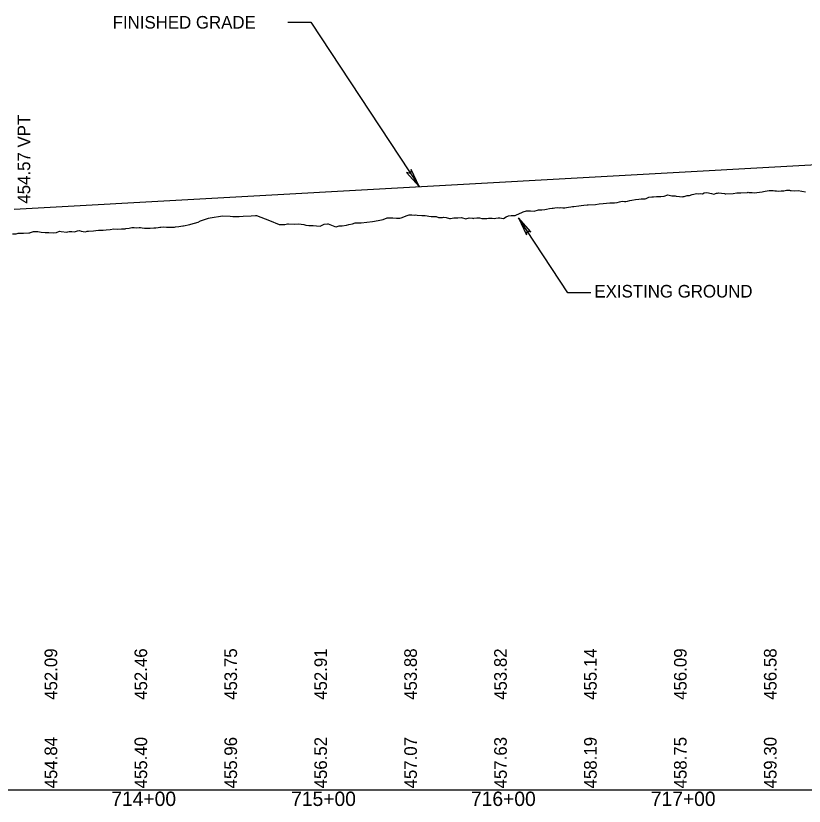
# Model space of a CAD drawing. Extents: x 2017200 to 2047700, y 854850 to 893350.
# Drawn here: x 2024326 to 2024764.4, y 889090.9 to 889530.3 of the extents above; entities that cross this region are included whole.
import ezdxf

# ---------------------------------------------------------------- set-up
doc = ezdxf.new("R2010")
doc.units = 0
for name, color, linetype in [('RD_DDB_Profile_EX', 7, 'Continuous'), ('RD_DDB_Profile_Lbl', 7, 'Continuous'), ('RD_DDB_Profile_PR', 7, 'Continuous'), ('RD_DDB_StaTX', 7, 'Continuous'), ('RD_DDB_StripGrade', 7, 'Continuous'), ('RD_GPK_Profile_Cell', 7, 'Continuous')]:
    doc.layers.add(name, color=color, linetype=linetype)

msp = doc.modelspace()

# ---------------------------------------------------------------- linework, layer by layer
at = {"layer": 'RD_DDB_Profile_EX'}
msp.add_lwpolyline([(2024324.24, 889409.11), (2024326.15, 889409.05), (2024327.38, 889409.46), (2024328.74, 889409.44), (2024329.5, 889409.49), (2024330.18, 889409.57), (2024333.24, 889409.68), (2024333.75, 889409.67), (2024334.21, 889409.78), (2024335.88, 889410.38), (2024338.23, 889410.39), (2024340.13, 889410.04), (2024342.26, 889409.85), (2024344.37, 889409.82), (2024346.74, 889409.65), (2024348.62, 889409.88), (2024350.32, 889410.57), (2024351.23, 889410.49), (2024354.34, 889410.11), (2024355, 889410.27), (2024355.73, 889410.37), (2024357.12, 889410.38), (2024358.37, 889410.28), (2024359.25, 889410.37), (2024360.23, 889410.74), (2024361.37, 889410.94), (2024362.4, 889410.68), (2024363.5, 889410.41), (2024364.73, 889410.3), (2024365.62, 889410.57), (2024366.42, 889410.64), (2024369.23, 889410.79), (2024370.45, 889410.95), (2024372, 889411.1), (2024373.73, 889411.18), (2024374.12, 889411.18), (2024374.48, 889411.16), (2024376.25, 889411.37), (2024378.51, 889411.62), (2024380.5, 889411.87), (2024382.73, 889411.8), (2024384.75, 889411.99), (2024386.56, 889411.99), (2024386.87, 889411.98), (2024387.22, 889412.03), (2024389, 889412.28), (2024390.59, 889412.61), (2024391.72, 889412.56), (2024393.25, 889412.45), (2024394.61, 889412.6), (2024395.37, 889412.65), (2024396.22, 889412.49), (2024397.5, 889412.27), (2024398.64, 889412.29), (2024400.72, 889412.33), (2024402.67, 889412.39), (2024403.87, 889412.49), (2024405.22, 889412.68), (2024406, 889412.8), (2024406.7, 889412.92), (2024408.12, 889413), (2024409.72, 889412.91), (2024410.25, 889412.84), (2024410.72, 889412.75), (2024414.22, 889412.86), (2024414.75, 889412.94), (2024416.62, 889413.2), (2024418.78, 889413.5), (2024419.31, 889413.59), (2024422.8, 889414.23), (2024423.39, 889414.47), (2024427.37, 889415.7), (2024428.7, 889416.37), (2024433.1, 889417.78), (2024434.07, 889417.93), (2024440.86, 889419.07), (2024445.23, 889418.86), (2024446.74, 889418.78), (2024448.72, 889418.67), (2024450.18, 889418.77), (2024452.48, 889418.91), (2024456.91, 889419.18), (2024459.22, 889419.28), (2024459.8, 889419.31), (2024467.11, 889416.47), (2024472.42, 889414.4), (2024474.15, 889414.36), (2024475.02, 889414.26), (2024475.55, 889414.31), (2024477.06, 889414.63), (2024477.6, 889414.66), (2024480.79, 889414.49), (2024483.21, 889414.63), (2024484.62, 889414.46), (2024486.2, 889414.23), (2024486.75, 889414.11), (2024487.24, 889413.98), (2024488.87, 889413.8), (2024490.69, 889413.81), (2024491.27, 889413.77), (2024493.12, 889413.65), (2024495.29, 889413.44), (2024497.37, 889414.55), (2024499.32, 889414.67), (2024499.69, 889414.65), (2024503.35, 889413.13), (2024504.19, 889413.07), (2024505.87, 889413.48), (2024507.38, 889413.6), (2024509.96, 889413.93), (2024511.2, 889414.32), (2024513.23, 889414.6), (2024514.7, 889415.25), (2024517.98, 889415.25), (2024524.3, 889416), (2024527.43, 889416.56), (2024530.31, 889417.18), (2024532.41, 889418.02), (2024535.68, 889418.01), (2024537.75, 889417.81), (2024539.59, 889417.85), (2024540.18, 889418.01), (2024543.62, 889419.4), (2024544.12, 889419.48), (2024544.68, 889419.63), (2024546.25, 889419.73), (2024547.65, 889419.59), (2024548.37, 889419.6), (2024549.18, 889419.41), (2024551.67, 889419.35), (2024552.62, 889419.28), (2024553.68, 889419.27), (2024554.74, 889419.2), (2024555.7, 889418.95), (2024556.87, 889418.76), (2024558.18, 889418.77), (2024559.73, 889418.71), (2024561.12, 889418.17), (2024562.67, 889418.19), (2024563.24, 889418.22), (2024563.76, 889418.31), (2024565.37, 889418.25), (2024567.17, 889417.72), (2024567.78, 889417.6), (2024569.62, 889418.06), (2024571.81, 889417.98), (2024573.87, 889418.14), (2024576.17, 889417.54), (2024578.12, 889418.02), (2024579.86, 889417.84), (2024580.24, 889417.72), (2024580.67, 889417.8), (2024582.37, 889418.07), (2024583.89, 889417.99), (2024585.17, 889417.69), (2024587.92, 889417.62), (2024588.74, 889417.87), (2024589.67, 889417.83), (2024590.87, 889417.85), (2024591.95, 889417.72), (2024592.99, 889417.75), (2024594.16, 889418.04), (2024595.12, 889418.05), (2024595.97, 889417.85), (2024597.24, 889417.72), (2024598.66, 889418.5), (2024600, 889419.11), (2024601.49, 889419.23), (2024603.16, 889419.29), (2024603.62, 889419.32), (2024604.03, 889419.43), (2024607.66, 889421.17), (2024608.05, 889421.33), (2024609.99, 889421.87), (2024612.16, 889421.96), (2024614.24, 889421.79), (2024616.66, 889422.53), (2024618.49, 889422.39), (2024620.14, 889422.73), (2024621.16, 889422.9), (2024622.74, 889423.3), (2024624.16, 889423.35), (2024624.87, 889423.43), (2024625.66, 889423.52), (2024626.99, 889423.71), (2024628.19, 889423.66), (2024629.12, 889423.72), (2024630.15, 889423.64), (2024631.24, 889423.62), (2024632.22, 889423.72), (2024633.37, 889423.92), (2024634.65, 889424.12), (2024635.49, 889424.29), (2024636.24, 889424.37), (2024639.15, 889424.74), (2024640.27, 889424.89), (2024641.87, 889425.01), (2024643.65, 889425.18), (2024643.99, 889425.25), (2024644.3, 889425.26), (2024648.33, 889425.44), (2024650.37, 889425.73), (2024652.65, 889426.05), (2024656.38, 889426.42), (2024656.74, 889426.45), (2024657.15, 889426.42), (2024658.87, 889426.43), (2024660.41, 889426.59), (2024661.65, 889426.93), (2024663.12, 889427.26), (2024664.43, 889427.15), (2024665.24, 889427.08), (2024666.14, 889427.32), (2024667.37, 889427.66), (2024668.46, 889427.92), (2024670.64, 889428.13), (2024672.49, 889428.49), (2024673.74, 889428.64), (2024675.14, 889428.62), (2024675.87, 889428.63), (2024676.52, 889428.8), (2024677.99, 889429.52), (2024679.64, 889429.65), (2024680.54, 889429.71), (2024682.24, 889429.83), (2024684.57, 889429.91), (2024686.49, 889430), (2024688.64, 889430.79), (2024690.74, 889430.34), (2024692.62, 889430.16), (2024693.14, 889430.07), (2024694.99, 889429.81), (2024696.65, 889429.77), (2024697.12, 889429.84), (2024697.63, 889429.95), (2024699.24, 889430.41), (2024700.68, 889430.52), (2024702.13, 889430.99), (2024704.71, 889431.46), (2024705.62, 889431.41), (2024706.63, 889431.47), (2024707.74, 889431.35), (2024708.73, 889431.83), (2024709.87, 889432.16), (2024711.13, 889431.92), (2024711.99, 889431.65), (2024712.76, 889431.53), (2024714.12, 889431.15), (2024715.63, 889431.66), (2024716.24, 889431.79), (2024716.79, 889431.93), (2024718.37, 889431.76), (2024720.13, 889431.46), (2024720.49, 889431.39), (2024720.82, 889431.37), (2024724.84, 889431.5), (2024726.87, 889431.93), (2024729.13, 889431.86), (2024732.9, 889432.16), (2024733.24, 889432.21), (2024733.62, 889432.19), (2024735.37, 889432.09), (2024736.92, 889431.97), (2024738.12, 889432.06), (2024740.95, 889432.54), (2024741.74, 889432.69), (2024742.62, 889432.89), (2024743.87, 889433), (2024744.98, 889433.22), (2024745.99, 889433.18), (2024747.12, 889433.15), (2024748.12, 889433), (2024749.01, 889433.07), (2024750.24, 889432.87), (2024751.62, 889433.01), (2024752.37, 889433.03), (2024753.03, 889433.11), (2024754.49, 889433.43), (2024756.12, 889433.33), (2024756.61, 889433.28), (2024757.06, 889433.29), (2024758.74, 889433.09), (2024761.09, 889433.13), (2024762.99, 889432.88), (2024765.12, 889432.4)], dxfattribs=at)
at = {"layer": 'RD_DDB_Profile_Lbl'}
for p, q in [((2024632.94, 889376.32), (2024605.48, 889418.04)), ((2024645.8, 889376.32), (2024632.94, 889376.32))]:
    msp.add_line(p, q, dxfattribs=at)
msp.add_lwpolyline([(2024477.18, 889526.8), (2024490.04, 889526.8), (2024550.21, 889435.4)], dxfattribs=at)
for points in [[(2024550.21, 889435.4), (2024545.75, 889444.9), (2024545.38, 889442.74), (2024543.25, 889443.25)], [(2024605.48, 889418.04), (2024609.94, 889408.54), (2024610.31, 889410.7), (2024612.44, 889410.19)]]:
    msp.add_lwpolyline(points, close=True, dxfattribs=at)
at = {"layer": 'RD_DDB_Profile_PR'}
msp.add_line((2024325, 889422.83), (2025645, 889496.42), dxfattribs=at)
at = {"layer": 'RD_GPK_Profile_Cell'}
msp.add_line((2020500, 889100), (2027000, 889100), dxfattribs=at)

# ---------------------------------------------------------------- texts
at = {"layer": 'RD_DDB_Profile_Lbl'}
for s, p in [('FINISHED GRADE', (2024379.86, 889523.24)), ('EXISTING GROUND', (2024647.74, 889373.71))]:
    msp.add_text(s, height=7, dxfattribs=at).set_placement(p)
at = {"layer": 'RD_DDB_StaTX'}
for s, p in [('714+00', (2024379.1, 889091)), ('715+00', (2024479.1, 889091)), ('716+00', (2024579.1, 889091)), ('717+00', (2024679.1, 889091))]:
    msp.add_text(s, height=8, dxfattribs=at).set_placement(p)
at = {"layer": 'RD_DDB_StripGrade'}
for s, p in [('454.57 VPT', (2024333.98, 889425.9)), ('452.09', (2024349, 889150)), ('452.46', (2024399, 889150)), ('453.75', (2024449, 889150)), ('452.91', (2024499, 889150)), ('453.88', (2024549, 889150)), ('453.82', (2024599, 889150)), ('455.14', (2024649, 889150)), ('456.09', (2024699, 889150)), ('456.58', (2024749, 889150)), ('454.84', (2024349, 889100.75)), ('455.40', (2024399, 889100.75)), ('455.96', (2024449, 889100.75)), ('456.52', (2024499, 889100.75)), ('457.07', (2024549, 889100.75)), ('457.63', (2024599, 889100.75)), ('458.19', (2024649, 889100.75)), ('458.75', (2024699, 889100.75)), ('459.30', (2024749, 889100.75))]:
    msp.add_text(s, height=7, rotation=90, dxfattribs=at).set_placement(p)

doc.saveas('drawing.dxf')
